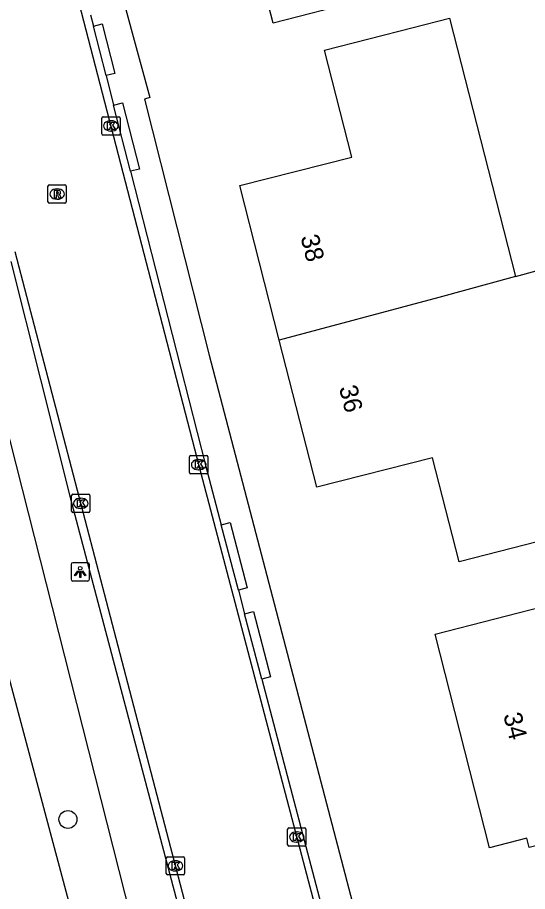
# Model space of a CAD drawing. Extents: x 162157 to 163165, y 378998 to 380775.
# Drawn here: x 162657.78 to 162685.7, y 380504.1 to 380551.95 of the extents above; entities that cross this region are included whole.
import ezdxf

# ---------------------------------------------------------------- set-up
doc = ezdxf.new("R2010")
doc.units = 0
for name, color, linetype in [('IMGEO_Boom', 7, 'Continuous'), ('IMGEO_Groenvoorziening', 7, 'Continuous'), ('IMGEO_Kolk', 7, 'Continuous'), ('IMGEO_Lichtpunt', 7, 'Continuous'), ('IMGEO_Pand', 7, 'Continuous'), ('IMGEO_Pand_nummerreeks', 7, 'Continuous'), ('IMGEO_Rijbaan_lokaal_gesloten', 7, 'Continuous'), ('IMGEO_Rijbaan_lokaal_open', 7, 'Continuous'), ('IMGEO_Rioolput', 7, 'Continuous'), ('IMGEO_Voetpad_open', 7, 'Continuous')]:
    doc.layers.add(name, color=color, linetype=linetype)

msp = doc.modelspace()

# ---------------------------------------------------------------- linework, layer by layer
at = {"layer": 'IMGEO_Boom'}
msp.add_circle((162660.541, 380508.047), 0.489, dxfattribs=at)
at = {"layer": 'IMGEO_Groenvoorziening'}
for points in [[(162655.034, 380537.94), (162664.661, 380500), (162670.147, 380478.375)], [(162667.543, 380477.694), (162661.54, 380500), (162651.656, 380537.009)]]:
    msp.add_lwpolyline(points, dxfattribs=at)
at = {"layer": 'IMGEO_Kolk'}
for p, q in [((162662.469, 380546.51), (162663.321, 380546.51)), ((162662.394, 380545.584), (162662.394, 380546.436)), ((162662.882, 380546.29), (162662.907, 380546.29)), ((162663.395, 380546.436), (162663.395, 380545.584)), ((162663.321, 380545.51), (162662.469, 380545.51)), ((162662.905, 380545.73), (162662.88, 380545.73)), ((162667.199, 380527.044), (162667.199, 380527.896)), ((162667.274, 380527.97), (162668.126, 380527.97)), ((162668.2, 380527.896), (162668.2, 380527.044)), ((162667.687, 380527.75), (162667.712, 380527.75)), ((162668.126, 380526.97), (162667.274, 380526.97)), ((162667.71, 380527.19), (162667.685, 380527.19)), ((162660.742, 380524.925), (162660.742, 380525.777)), ((162660.817, 380525.851), (162661.669, 380525.851)), ((162661.23, 380525.631), (162661.255, 380525.631)), ((162661.743, 380525.777), (162661.743, 380524.925)), ((162661.253, 380525.071), (162661.228, 380525.071)), ((162661.669, 380524.851), (162660.817, 380524.851)), ((162672.567, 380506.661), (162672.567, 380507.513)), ((162672.642, 380507.587), (162673.494, 380507.587)), ((162673.055, 380507.367), (162673.08, 380507.367)), ((162673.568, 380507.513), (162673.568, 380506.661)), ((162673.078, 380506.807), (162673.053, 380506.807)), ((162673.494, 380506.587), (162672.642, 380506.587)), ((162665.924, 380505.082), (162665.924, 380505.934)), ((162665.999, 380506.008), (162666.851, 380506.008)), ((162666.925, 380505.934), (162666.925, 380505.082)), ((162666.412, 380505.788), (162666.437, 380505.788)), ((162666.851, 380505.008), (162665.999, 380505.008)), ((162666.435, 380505.228), (162666.41, 380505.228))]:
    msp.add_line(p, q, dxfattribs=at)
for points in [[(162662.469, 380546.51), (162663.321, 380546.51)], [(162662.394, 380545.584), (162662.394, 380546.436)], [(162662.715, 380546.21), (162662.838, 380546.21), (162662.838, 380546.059), (162662.968, 380546.21), (162663.132, 380546.21), (162662.986, 380546.059), (162663.139, 380545.81), (162662.987, 380545.81), (162662.902, 380545.974), (162662.838, 380545.907), (162662.838, 380545.81), (162662.715, 380545.81), (162662.715, 380546.21)], [(162663.395, 380546.436), (162663.395, 380545.584)], [(162663.321, 380545.51), (162662.469, 380545.51)], [(162667.199, 380527.044), (162667.199, 380527.896)], [(162667.274, 380527.97), (162668.126, 380527.97)], [(162668.2, 380527.896), (162668.2, 380527.044)], [(162667.52, 380527.67), (162667.643, 380527.67), (162667.643, 380527.519), (162667.773, 380527.67), (162667.937, 380527.67), (162667.791, 380527.519), (162667.944, 380527.27), (162667.792, 380527.27), (162667.707, 380527.434), (162667.643, 380527.367), (162667.643, 380527.27), (162667.52, 380527.27), (162667.52, 380527.67)], [(162668.126, 380526.97), (162667.274, 380526.97)], [(162660.742, 380524.925), (162660.742, 380525.777)], [(162660.817, 380525.851), (162661.669, 380525.851)], [(162661.063, 380525.551), (162661.186, 380525.551), (162661.186, 380525.4), (162661.316, 380525.551), (162661.48, 380525.551), (162661.334, 380525.4), (162661.487, 380525.151), (162661.335, 380525.151), (162661.25, 380525.315), (162661.186, 380525.248), (162661.186, 380525.151), (162661.063, 380525.151), (162661.063, 380525.551)], [(162661.743, 380525.777), (162661.743, 380524.925)], [(162661.669, 380524.851), (162660.817, 380524.851)], [(162672.567, 380506.661), (162672.567, 380507.513)], [(162672.642, 380507.587), (162673.494, 380507.587)], [(162672.888, 380507.287), (162673.011, 380507.287), (162673.011, 380507.136), (162673.141, 380507.287), (162673.305, 380507.287), (162673.159, 380507.136), (162673.312, 380506.887), (162673.16, 380506.887), (162673.075, 380507.051), (162673.011, 380506.984), (162673.011, 380506.887), (162672.888, 380506.887), (162672.888, 380507.287)], [(162673.568, 380507.513), (162673.568, 380506.661)], [(162673.494, 380506.587), (162672.642, 380506.587)], [(162665.924, 380505.082), (162665.924, 380505.934)], [(162665.999, 380506.008), (162666.851, 380506.008)], [(162666.925, 380505.934), (162666.925, 380505.082)], [(162666.245, 380505.708), (162666.368, 380505.708), (162666.368, 380505.557), (162666.498, 380505.708), (162666.662, 380505.708), (162666.516, 380505.557), (162666.669, 380505.308), (162666.517, 380505.308), (162666.432, 380505.472), (162666.368, 380505.405), (162666.368, 380505.308), (162666.245, 380505.308), (162666.245, 380505.708)], [(162666.851, 380505.008), (162665.999, 380505.008)]]:
    msp.add_lwpolyline(points, dxfattribs=at)
for centre, start, end in [((162662.471, 380546.434), 91.552, 178.448), ((162662.471, 380546.434), 91.552, 178.448), ((162663.319, 380546.434), 1.552, 88.448), ((162663.319, 380546.434), 1.552, 88.448), ((162662.471, 380545.586), 181.552, 268.448), ((162662.471, 380545.586), 181.552, 268.448), ((162663.319, 380545.586), 271.552, 358.448), ((162663.319, 380545.586), 271.552, 358.448), ((162667.276, 380527.894), 91.552, 178.448), ((162667.276, 380527.894), 91.552, 178.448), ((162668.124, 380527.894), 1.552, 88.448), ((162668.124, 380527.894), 1.552, 88.448), ((162667.276, 380527.046), 181.552, 268.448), ((162667.276, 380527.046), 181.552, 268.448), ((162668.124, 380527.046), 271.552, 358.448), ((162668.124, 380527.046), 271.552, 358.448), ((162660.819, 380525.775), 91.552, 178.448), ((162660.819, 380525.775), 91.552, 178.448), ((162661.667, 380525.775), 1.552, 88.448), ((162661.667, 380525.775), 1.552, 88.448), ((162660.819, 380524.927), 181.552, 268.448), ((162660.819, 380524.927), 181.552, 268.448), ((162661.667, 380524.927), 271.552, 358.448), ((162661.667, 380524.927), 271.552, 358.448), ((162672.644, 380507.511), 91.552, 178.448), ((162672.644, 380507.511), 91.552, 178.448), ((162673.492, 380507.511), 1.552, 88.448), ((162673.492, 380507.511), 1.552, 88.448), ((162672.644, 380506.663), 181.552, 268.448), ((162672.644, 380506.663), 181.552, 268.448), ((162673.492, 380506.663), 271.552, 358.448), ((162673.492, 380506.663), 271.552, 358.448), ((162666.001, 380505.932), 91.552, 178.448), ((162666.001, 380505.932), 91.552, 178.448), ((162666.849, 380505.932), 1.552, 88.448), ((162666.849, 380505.932), 1.552, 88.448), ((162666.001, 380505.084), 181.552, 268.448), ((162666.001, 380505.084), 181.552, 268.448), ((162666.849, 380505.084), 271.552, 358.448), ((162666.849, 380505.084), 271.552, 358.448)]:
    msp.add_arc(centre, 0.0765, start, end, dxfattribs=at)
for centre, major_axis, ratio, start_param, end_param in [((162662.881, 380546.01), (-0.387, 0.002), 0.722429, 4.712389, 7.853982), ((162662.906, 380546.01), (-0.39, 0.002), 0.717154, 1.570796, 4.712389), ((162667.686, 380527.47), (-0.387, 0.002), 0.722429, 4.712389, 7.853982), ((162667.711, 380527.47), (-0.39, 0.002), 0.717154, 1.570796, 4.712389), ((162661.229, 380525.351), (-0.387, 0.002), 0.722429, 4.712389, 7.853982), ((162661.254, 380525.351), (-0.39, 0.002), 0.717154, 1.570796, 4.712389), ((162673.054, 380507.087), (-0.387, 0.002), 0.722429, 4.712389, 7.853982), ((162673.079, 380507.087), (-0.39, 0.002), 0.717154, 1.570796, 4.712389), ((162666.411, 380505.508), (-0.387, 0.002), 0.722429, 4.712389, 7.853982), ((162666.436, 380505.508), (-0.39, 0.002), 0.717154, 1.570796, 4.712389)]:
    msp.add_ellipse(centre, major_axis=major_axis, ratio=ratio, start_param=start_param, end_param=end_param, dxfattribs=at)
at = {"layer": 'IMGEO_Lichtpunt'}
for p, q in [((162661.619, 380522.096), (162660.811, 380522.096)), ((162661.619, 380522.096), (162660.811, 380522.096)), ((162660.717, 380522.001), (162660.717, 380521.194)), ((162660.717, 380522.001), (162660.717, 380521.194)), ((162661.713, 380521.194), (162661.713, 380522.001)), ((162661.713, 380521.194), (162661.713, 380522.001)), ((162660.811, 380521.1), (162661.619, 380521.1)), ((162660.811, 380521.1), (162661.619, 380521.1))]:
    msp.add_line(p, q, dxfattribs=at)
for points in [[(162661.091, 380521.665), (162661.13, 380521.637), (162660.942, 380521.375), (162660.904, 380521.402), (162661.091, 380521.665)], [(162661.193, 380521.617), (162661.24, 380521.617), (162661.24, 380521.295), (162661.193, 380521.295), (162661.193, 380521.617)], [(162661.303, 380521.637), (162661.341, 380521.664), (162661.528, 380521.402), (162661.489, 380521.374), (162661.303, 380521.637)]]:
    msp.add_lwpolyline(points, dxfattribs=at)
msp.add_circle((162661.216, 380521.799), 0.0994, dxfattribs=at)
for centre, start, end in [((162660.811, 380522.001), 90, 180), ((162660.811, 380522.001), 90, 180), ((162661.619, 380522.001), 0, 90), ((162661.619, 380522.001), 0, 90), ((162660.811, 380521.194), 180, 270), ((162660.811, 380521.194), 180, 270), ((162661.619, 380521.194), 270, 0), ((162661.619, 380521.194), 270, 360)]:
    msp.add_arc(centre, 0.0946, start, end, dxfattribs=at)
at = {"layer": 'IMGEO_Pand'}
for points in [[(162674.891, 380565.17), (162675.412, 380565.31), (162678.155, 380566.022), (162678.193, 380565.875), (162679.111, 380562.278), (162679.945, 380562.491), (162681.067, 380558.092), (162680.234, 380557.879), (162681.213, 380554.042), (162676.612, 380552.868), (162671.767, 380551.632), (162670.826, 380555.319), (162668.736, 380554.785), (162666.65, 380562.964)], [(162672.107, 380534.283), (162669.949, 380542.743), (162676.08, 380544.307), (162674.587, 380550.159), (162679.432, 380551.396), (162681.43, 380551.906), (162685.037, 380537.771)], [(162685.037, 380537.771), (162687.294, 380538.389), (162689.384, 380530.202), (162690.848, 380524.467)], [(162685.037, 380537.771), (162680.852, 380536.625), (162672.107, 380534.283)], [(162686.305, 380523.266), (162681.949, 380522.154), (162680.496, 380527.85), (162674.16, 380526.233), (162672.107, 380534.283)], [(162690.848, 380524.467), (162692.117, 380524.791), (162694.264, 380525.339), (162694.616, 380525.429), (162695.536, 380521.821), (162696.472, 380518.15), (162693.348, 380517.353), (162690.221, 380516.555), (162692.208, 380508.765), (162686.297, 380507.257), (162686.443, 380506.682), (162685.789, 380506.515), (162685.661, 380507.016), (162683.618, 380506.495), (162680.634, 380518.191), (162687.174, 380519.86), (162686.305, 380523.266)]]:
    msp.add_lwpolyline(points, dxfattribs=at)
at = {"layer": 'IMGEO_Rijbaan_lokaal_gesloten'}
for points in [[(162657.91, 380565.281), (162660.014, 380557.121), (162667.731, 380527.348), (162674.932, 380500), (162681.65, 380474.495), (162683.015, 380468.663), (162684.023, 380462.108), (162684.831, 380454.251), (162685.204, 380450.618)], [(162678.535, 380447.716), (162678.253, 380450.55), (162677.316, 380459.965), (162676.381, 380466.512), (162675.002, 380472.733), (162670.658, 380489.297), (162667.863, 380500), (162657.649, 380539.117)], [(162657.416, 380538.596), (162660.655, 380525.668), (162667.446, 380500), (162672.577, 380480.608)]]:
    msp.add_lwpolyline(points, dxfattribs=at)
at = {"layer": 'IMGEO_Rijbaan_lokaal_open'}
for points in [[(162661.78, 380552.096), (162661.941, 380551.466)], [(162662.63, 380548.763), (162661.941, 380551.466)], [(162662.63, 380548.763), (162663.041, 380547.154)], [(162663.966, 380543.528), (162663.041, 380547.154)], [(162663.966, 380543.528), (162668.07, 380527.436), (162668.931, 380524.168)], [(162669.869, 380520.603), (162668.931, 380524.168)], [(162669.869, 380520.603), (162670.213, 380519.296)], [(162671.153, 380515.728), (162670.213, 380519.296)], [(162671.153, 380515.728), (162675.319, 380499.905)]]:
    msp.add_lwpolyline(points, dxfattribs=at)
at = {"layer": 'IMGEO_Rioolput'}
for p, q in [((162659.447, 380541.854), (162659.447, 380542.706)), ((162659.522, 380542.78), (162660.374, 380542.78)), ((162660.448, 380542.706), (162660.448, 380541.854)), ((162659.935, 380542.56), (162659.96, 380542.56)), ((162660.374, 380541.78), (162659.522, 380541.78)), ((162659.958, 380542), (162659.933, 380542))]:
    msp.add_line(p, q, dxfattribs=at)
for points in [[(162659.447, 380541.854), (162659.447, 380542.706)], [(162659.522, 380542.78), (162660.374, 380542.78)], [(162660.448, 380542.706), (162660.448, 380541.854)], [(162660.036, 380542.478), (162659.784, 380542.48), (162659.784, 380542.08)], [(162659.784, 380542.08), (162659.908, 380542.08), (162659.908, 380542.242), (162659.919, 380542.242)], [(162659.962, 380542.399), (162659.908, 380542.399), (162659.908, 380542.318)], [(162659.908, 380542.318), (162659.96, 380542.318)], [(162659.966, 380542.213), (162660.037, 380542.08), (162660.177, 380542.08), (162660.112, 380542.206)], [(162660.374, 380541.78), (162659.522, 380541.78)]]:
    msp.add_lwpolyline(points, dxfattribs=at)
for centre, radius, start, end in [((162659.524, 380542.704), 0.0765, 91.552, 178.448), ((162659.524, 380542.704), 0.0765, 91.552, 178.448), ((162660.372, 380542.704), 0.0765, 1.552, 88.448), ((162660.372, 380542.704), 0.0765, 1.552, 88.448), ((162659.918, 380542.189), 0.0533, 26.0293, 88.6989), ((162659.944, 380542.507), 0.19, 274.7715, 282.9687), ((162659.968, 380542.303), 0.0964, 77.0061, 93.1865), ((162659.982, 380542.36), 0.0378, 276.6634, 79.6772), ((162660.035, 380542.368), 0.109, 350.3612, 89.416), ((162660.033, 380542.368), 0.112, 277.5842, 350.9817), ((162660.017, 380542.153), 0.108, 29.5134, 73.7905), ((162659.524, 380541.856), 0.0765, 181.552, 268.448), ((162659.524, 380541.856), 0.0765, 181.552, 268.448), ((162660.372, 380541.856), 0.0765, 271.552, 358.448), ((162660.372, 380541.856), 0.0765, 271.552, 358.448)]:
    msp.add_arc(centre, radius, start, end, dxfattribs=at)
for centre, major_axis, ratio, start_param, end_param in [((162659.934, 380542.28), (-0.387, 0.002), 0.722429, 4.712389, 7.853982), ((162659.959, 380542.28), (-0.39, 0.002), 0.717154, 1.570796, 4.712389)]:
    msp.add_ellipse(centre, major_axis=major_axis, ratio=ratio, start_param=start_param, end_param=end_param, dxfattribs=at)
at = {"layer": 'IMGEO_Voetpad_open'}
for points in [[(162663.653, 380552.582), (162663.926, 380551.586), (162664.002, 380551.31), (162665.03, 380547.56), (162664.729, 380547.475), (162668.276, 380533.465), (162677.031, 380500), (162683.958, 380473.523)], [(162661.941, 380551.466), (162662.424, 380551.592), (162663.115, 380548.885), (162662.63, 380548.763)], [(162663.041, 380547.154), (162663.525, 380547.276), (162664.45, 380543.65), (162663.966, 380543.528)], [(162668.931, 380524.168), (162669.414, 380524.294), (162670.352, 380520.729), (162669.869, 380520.603)], [(162670.213, 380519.296), (162670.696, 380519.422), (162671.636, 380515.854), (162671.153, 380515.728)]]:
    msp.add_lwpolyline(points, dxfattribs=at)

# ---------------------------------------------------------------- texts
at = {"layer": 'IMGEO_Pand_nummerreeks'}
for s, rotation, p in [('38', 284.31, (162673.266, 380539.934)), ('36', 284.3065, (162675.372, 380531.682)), ('34', 284.3123, (162684.364, 380513.767))]:
    msp.add_text(s, height=1, rotation=rotation, dxfattribs=at).set_placement(p)

doc.saveas('drawing.dxf')
